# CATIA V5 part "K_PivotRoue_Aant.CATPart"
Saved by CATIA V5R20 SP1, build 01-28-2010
Part number: pivot_roue_avant_volume
Publications: "épaisseur pivot", "épaisseur moyeux", "diamètre moyeux", "diamètre tube pivot"
Bounding box of the stored display mesh (mm): x 612.511 to 875, y -177.979 to 25, z -127.979 to -72.021
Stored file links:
  G:\Khaled_CFAO_2011\ST2M\ST2M_GR1\cdurantin\cdurantin\Khaled\CAD_ThinkMOTION\K_PivotRoue_Aant.CATPart
  C:\Documents and Settings\cdurantin\Bureau\cdurantin\caddy.CATProduct
  G:\Khaled_CFAO_2011\ST2M\ST2M_GR1\cdurantin\cdurantin\CATIA\pivot roue avant.CATPart
  G:\Khaled_CFAO_2011\ST2M\ST2M_GR1\cdurantin\cdurantin\CATIA\Corps.CATPart
  G:\Khaled_CFAO_2011\ST2M\ST2M_GR1\cdurantin\cdurantin\CATIA\corps_volume.CATPart
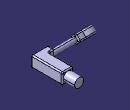
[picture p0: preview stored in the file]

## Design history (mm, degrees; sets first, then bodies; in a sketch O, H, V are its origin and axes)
Parameters
  `épaisseur pivot` = 7.5 mm
  `épaisseur moyeux` = 50 mm
  `diamètre moyeux` = 100 mm
  `diamètre tube pivot` = 20 mm
External parameters (linked from other documents)
  `External.diamètre des barres` = 40 mm
  `External.Surepaisseur du tube` = 10 mm
  `External.diamètre doight pivot roue avant` = 5 mm
  `External.hauteur roue avant` = 100 mm
Set1
  Plane1: linked copy from another document
  Line1: linked copy from another document
  Line2: linked copy from another document
  Point1: linked copy from another document
  Line3: linked copy from another document
  DatumCurve1: linked copy from another document
  Line4: linked copy from another document
  Point2: linked copy from another document
  Line5: linked copy from another document
Body1 (main body)
  Sketch1 on Plane1, origin (0, -25, 25), H (-1, 0, 0), V (0, 0.7071, 0.7071)
    reference projected point E1 (-640, -176.7767) from Line1
    circle A1 centre (-640, -176.7767) radius 20
    arc A2 centre (-640, -176.7767) radius 27.5 from (-663.0489, -191.7767) to (-663.0489, -161.7767) ccw
    line L1 (-663.0489, -161.7767) -> (-693.0489, -161.7767)
    line L2 (-693.0489, -161.7767) -> (-693.0489, -191.7767)
    line L3 (-693.0489, -191.7767) -> (-663.0489, -191.7767)
    radius A1 = 20 {= `External.diamètre des barres` /2}
    radius A2 = 27.5 {= `épaisseur pivot` +`External.diamètre des barres` /2}
    length L2 = 30 {= `diamètre tube pivot`  +`External.Surepaisseur du tube`}
    length L1 = 30 {= `diamètre tube pivot`  +`External.Surepaisseur du tube`}
    length L3 = 30 {= `diamètre tube pivot` +`External.Surepaisseur du tube`}
    concentricity: A1 E1, A2 A1
    horizontal: L1 H, L3 H
    vertical: L2 V
  Pad1: profile Sketch1, direction (0, 0.7071, -0.7071), length 15 {= (`diamètre tube pivot`  +`External.Surepaisseur du tube` )/2}, mirrored extent
  Sketch2 on Plane1, origin (0, -25, 25), H (-1, 0, 0), V (0, 0.7071, 0.7071)
    arc A1 centre (-640, -176.7767) radius 20 from (-620.1569, -179.2767) to (-659.8431, -179.2767) ccw
    reference projected point E1 (-640, -176.7767) from Point1
    arc A2 centre (-640, -176.7767) radius 22.5 from (-617.6393, -179.2767) to (-662.3607, -179.2767) ccw
    line L1 (-617.6393, -179.2767) -> (-620.1569, -179.2767)
    point P5 (-659.8431, -179.2767)
    line L2 (-659.8431, -179.2767) -> (-662.3607, -179.2767)
    reference projected line E2 (50, -176.7767) -> (-720, -176.7767) from Line3
    radius A1 = 20 {= `External.diamètre des barres` /2}
    radius A2 = 22.5 {= `External.diamètre des barres` /2+`External.diamètre doight pivot roue avant` /2}
    distance L1 E2 = 2.5 {= `External.diamètre doight pivot roue avant` /2}
    concentricity: E1 A1, A2 A1
    horizontal: L1 H, L2 H
    coincidence: P5 L1
  Pocket1: profile Sketch2, direction (0, -0.7071, 0.7071), length 3.5 {= `External.diamètre doight pivot roue avant` /2+1mm}, mirrored extent
  Fillet1: radius 5, on edge [start face of Pad1 | face of Pad1 from Sketch1.L1]; edge [face of Pad1 from Sketch1.L1 | end face of Pad1]; edge [face of Pad1 from Sketch1.L2 | face of Pad1 from Sketch1.L1]; edge [start face of Pad1 | face of Pad1 from Sketch1.L2]; edge [start face of Pad1 | face of Pad1 from Sketch1.L3]; edge [face of Pad1 from Sketch1.L3 | end face of Pad1]; edge [face of Pad1 from Sketch1.L3 | face of Pad1 from Sketch1.L2]; edge [face of Pad1 from Sketch1.L2 | end face of Pad1]; edge [start face of Pad1 | face of Pad1 from Sketch1.A2]; edge [face of Pad1 from Sketch1.A2 | end face of Pad1]
  Sketch3 on face of Pad1 from Sketch1.L2, origin (693.0489, -72.8664, -46.0027), H (0, 1, 0), V (0, 0, 1)
    point P1 (-77.1336, -53.9973)
    reference projected point E1 (-77.1336, -53.9973) from Line2
    distance E1 P1 = 0
  Hole1: placed by Sketch3, at (693.0489, -150, -100) direction (-1, 0, 0), diameter 20 {= `diamètre tube pivot`}, depth 20 {= `diamètre tube pivot`}
  Sketch4 on Plane1, origin (0, -25, 25), H (-1, 0, 0), V (0, 0.7071, 0.7071)
    line L1 (-830, -166.7767) -> (-660, -166.7767)
    line L2 (-660, -166.7767) -> (-660, -176.7767)
    line L3 (-660, -176.7767) -> (-830, -176.7767)
    line L4 (-830, -176.7767) -> (-830, -166.7767)
    reference projected point E5 (-850, -176.7767) from Point2
    reference projected point E6 (-640, -176.7767) from Line4
    reference projected line E7 (-640, -176.7767) -> (-800, -176.7767) from Line2
    distance E5 L4 = 20 {= `diamètre tube pivot`}
    distance E6 L2 = 20 {= `diamètre tube pivot`}
    distance E7 L3 = 0
    length L2 = 10 {= `diamètre tube pivot` /2}
    horizontal: L1 H, L3 H
    vertical: L2 V, L4 V
  Shaft1: profile Sketch4, axis Line2, angle 360
Body2 "raccord/roue"
  Plane2: type Offset, RefPlane xy-plane, Offset 100 {= `External.hauteur roue avant`}, reversed
  Sketch5 on Plane2, origin (0, 0, -100), H (1, 0, 0), V (0, 1, 0)
    line L1 (800, -135) -> (825, -135)
    line L2 (825, -135) -> (825, -25)
    line L3 (825, -25) -> (875, -25)
    line L4 (875, -25) -> (875, -165)
    line L5 (875, -165) -> (800, -165)
    line L6 (800, -165) -> (800, -135)
    reference projected line E1 (640, -150) -> (800, -150) from Line2
    reference projected line E2 (850, -70) -> (850, -20) from Line5
    reference projected line E3 (850, -70) -> (850, -20) from Line5
    length L6 = 30 {= `diamètre tube pivot` +`External.Surepaisseur du tube`}
    distance E1 L1 = 15 {= (`diamètre tube pivot`  +`External.Surepaisseur du tube` )/2}
    distance L6 E2 = 50 {= `External.diamètre des barres` +`External.Surepaisseur du tube`}
    distance H L3 = 25 {= `épaisseur moyeux` /2}
    length L3 = 50 {= `épaisseur moyeux`}
    distance L4 E3 = 25 {= `épaisseur moyeux` /2}
    horizontal: L1 H, L3 H, L5 H
    vertical: L2 V, L4 V, L6 V
  Pad2: profile Sketch5, direction (0, 0, 1), length 25 {= (`External.diamètre des barres` +`External.Surepaisseur du tube` )/2}, mirrored extent
  Fillet2: radius 5, on edge [face of Pad2 from Sketch5.L2 | face of Pad2 from Sketch5.L3]; edge [face of Pad2 from Sketch5.L2 | end face of Pad2]; edge [face of Pad2 from Sketch5.L1 | face of Pad2 from Sketch5.L2]; edge [start face of Pad2 | face of Pad2 from Sketch5.L2]; edge [face of Pad2 from Sketch5.L1 | end face of Pad2]; edge [face of Pad2 from Sketch5.L6 | face of Pad2 from Sketch5.L1]; edge [start face of Pad2 | face of Pad2 from Sketch5.L1]; edge [start face of Pad2 | face of Pad2 from Sketch5.L6]; edge [face of Pad2 from Sketch5.L6 | end face of Pad2]; edge [face of Pad2 from Sketch5.L5 | face of Pad2 from Sketch5.L6]; end face of Pad2; face of Pad2 from Sketch5.L3; face of Pad2 from Sketch5.L4; face of Pad2 from Sketch5.L5
  Sketch6 on face of Pad2 from Sketch5.L6, origin (800, -61.7431, -108.2569), H (0, 1, 0), V (0, 0, -1)
    point P1 (-88.2569, -8.2569)
    reference projected point E1 (-88.2569, -8.2569) from Line2
    distance E1 P1 = 0
  Hole2: placed by Sketch6, at (800, -150, -100) direction (1, 0, 0), diameter 20 {= `diamètre tube pivot`}, depth 20 {= `diamètre tube pivot`}
  Sketch7 on face of Pad2 from Sketch5.L3, origin (0, -25, 0), H (-1, 0, 0), V (0, 0, 1)
    circle A1 centre (-850, -100) radius 20
    reference projected point E1 (-850, -100) from Line5
    radius A1 = 20 {= `External.diamètre des barres` /2}
    concentricity: A1 E1
  Pad3: profile Sketch7, direction (0, 1, 0), length 50 {= `épaisseur moyeux`}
